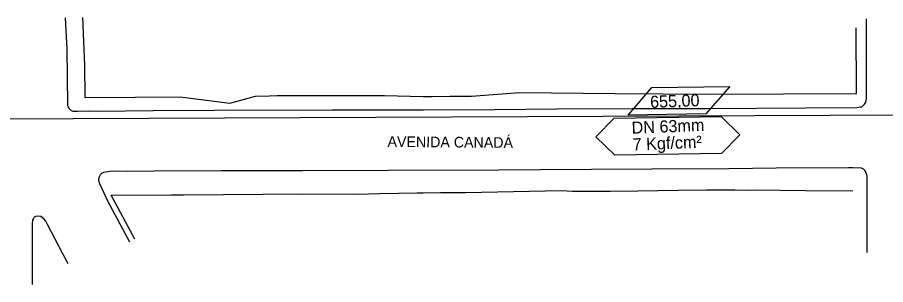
# Model space of a CAD drawing. Extents: x 325899 to 364828, y 7568995 to 7592502.
# Drawn here: x 355157 to 355911, y 7574728 to 7574960 of the extents above; entities that cross this region are included whole.
import ezdxf

# ---------------------------------------------------------------- set-up
doc = ezdxf.new("R2010")
doc.units = 0
for name, color, linetype in [('MEIO_FIO_GUIA', 7, 'Continuous'), ('MURO_DIVISA', 7, 'Continuous'), ('SIMBOLO', 7, 'Continuous'), ('TEXTO', 7, 'Continuous'), ('TUBO_PEAD_GN_63', 7, 'Continuous')]:
    doc.layers.add(name, color=color, linetype=linetype)

msp = doc.modelspace()

# ---------------------------------------------------------------- linework, layer by layer
at = {"layer": 'MEIO_FIO_GUIA'}
for p, q in [((355894.81, 7574889.12), (355894.72, 7574958.72)), ((355895.09, 7574811.47), (355894.97, 7574755.77))]:
    msp.add_line(p, q, dxfattribs=at)
for points in [[(355198.89, 7574959.44), (355200.38, 7574932.39), (355200.95, 7574884.1), (355201.41, 7574882.3), (355202.2, 7574881.09), (355203.31, 7574879.98), (355204.32, 7574879.14), (355206.02, 7574878.57), (355209.92, 7574878.41), (355219.34, 7574878.68), (355227, 7574878.58), (355275.28, 7574878.92), (355328.48, 7574879.3), (355430.84, 7574879.54), (355510.23, 7574879.75), (355571.98, 7574880.04), (355625.71, 7574880.43), (355691.18, 7574880.76), (355756.78, 7574880.82), (355841.94, 7574881.41), (355886.26, 7574881.77), (355888, 7574881.92), (355889.35, 7574882.1), (355890.61, 7574882.23), (355891.65, 7574883.24), (355892.95, 7574884.46), (355894.13, 7574886.28), (355894.8, 7574889.15)], [(355255.15, 7574764.58), (355236.17, 7574800.25), (355232.72, 7574807.17), (355229, 7574815.23), (355228.25, 7574817.99), (355228.23, 7574820.02), (355229.05, 7574822.4), (355229.81, 7574823.54), (355230.93, 7574824.62), (355232.46, 7574825.39), (355233.95, 7574825.71), (355236.01, 7574825.93), (355237.75, 7574826.4), (355245.5, 7574826.59), (355253.11, 7574826.38), (355276.35, 7574826.65), (355334.79, 7574826.82), (355405.09, 7574826.82), (355479.43, 7574827.15), (355575.46, 7574827.65), (355611.65, 7574827.82), (355655.91, 7574828.05), (355708.29, 7574828.27), (355775.17, 7574828.81), (355816.19, 7574829.21), (355879.03, 7574829.68), (355882.85, 7574829.65), (355890.03, 7574829.28), (355891.76, 7574828.32), (355892.82, 7574827.43), (355893.43, 7574826.36), (355894.21, 7574825.02), (355894.81, 7574823.5), (355894.9, 7574821.76), (355894.98, 7574818.92), (355895.09, 7574811.47)], [(355201.63, 7574745.91), (355200.65, 7574747.72), (355197.06, 7574754.63), (355183.78, 7574779.97), (355182.25, 7574782.93), (355180.41, 7574785.05), (355177.82, 7574786.85), (355175.1, 7574787.24), (355173.28, 7574787.11), (355172.2, 7574786.34), (355171.42, 7574785.34), (355170.73, 7574783.94), (355170.23, 7574780.77), (355170.42, 7574735.83), (355170.21, 7574727.81)]]:
    msp.add_lwpolyline(points, dxfattribs=at)
at = {"layer": 'MURO_DIVISA'}
for points in [[(355214.13, 7574959.93), (355215.77, 7574918.45), (355215.99, 7574890.25), (355259.83, 7574890.63), (355298.85, 7574890.95), (355341.91, 7574885.34), (355364.34, 7574891.61), (355376.37, 7574891.92), (355383.15, 7574892.06), (355476.15, 7574892.08), (355509.89, 7574891.25), (355517.72, 7574891.25), (355533.06, 7574891.52), (355551.64, 7574891.57), (355593.35, 7574894.82), (355676.62, 7574893.69), (355759.14, 7574893.36), (355886.04, 7574893.9), (355885.79, 7574950.94), (355885.79, 7574950.94)], [(355259.34, 7574767.39), (355238.97, 7574805.58), (355291.26, 7574805.74), (355301.85, 7574805.88), (355336.5, 7574806.21), (355405.41, 7574806.66), (355452.73, 7574806.31), (355472.06, 7574807.05), (355504.7, 7574807.58), (355509.68, 7574807.42), (355524.98, 7574807.87), (355546.42, 7574807.89), (355630.04, 7574809.55), (355639.55, 7574808.86), (355672.11, 7574809.05), (355696.1, 7574809.16), (355713.61, 7574809.62), (355731.1, 7574809.77), (355755.85, 7574810.13), (355780.43, 7574810.09), (355791.36, 7574809.8), (355798.05, 7574810.26), (355841.76, 7574809.69), (355882.84, 7574809.38)]]:
    msp.add_lwpolyline(points, dxfattribs=at)
at = {"layer": 'SIMBOLO'}
msp.add_lwpolyline([(355755.19, 7574876.02), (355687.72, 7574875.13), (355708.47, 7574899.1), (355775.95, 7574899.99)], close=True, dxfattribs=at)
msp.add_lwpolyline([(355659.86, 7574856.07), (355675.68, 7574872.4), (355768.46, 7574873.85), (355784.78, 7574858.03), (355768.96, 7574841.7), (355676.18, 7574840.25), (355659.86, 7574856.07)], dxfattribs=at)
at = {"layer": 'TUBO_PEAD_GN_63'}
msp.add_line((356604.1, 7574877.86), (354380.6, 7574868.2), dxfattribs=at)

# ---------------------------------------------------------------- texts
at = {"layer": 'TEXTO'}
for s, height, rotation, p in [('655,00', 10.5, 2.0817, (355706.98, 7574881.27)), ('DN 63mm', 10.5, 2.29067, (355690.98, 7574858.83)), ('AVENIDA CANADÁ', 9.2211, 359.50983, (355478.83, 7574847.46)), ('7 Kgf/cm²', 10.5, 2.29067, (355691.88, 7574844.33))]:
    msp.add_text(s, height=height, rotation=rotation, dxfattribs=at).set_placement(p)

doc.saveas('drawing.dxf')
